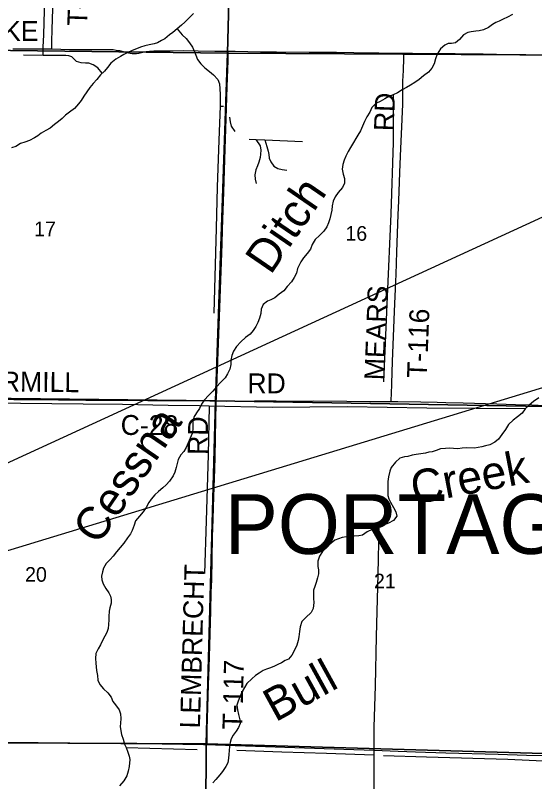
# Model space of a CAD drawing. Extents: x 0 to 39.4, y 0 to 22.
# Drawn here: x 6.833 to 8.317, y 17.227 to 19.416 of the extents above; entities that cross this region are included whole.
import ezdxf

# ---------------------------------------------------------------- set-up
doc = ezdxf.new("R2010")
doc.units = 0
for name, color, linetype in [('GM_X_County_Road', 7, 'Continuous'), ('GM_X_County_Road_Text', 7, 'Continuous'), ('GM_X_Major_River', 7, 'Continuous'), ('GM_X_Minor_River', 7, 'Continuous'), ('GM_X_Minor_River_Text', 7, 'Continuous'), ('GM_X_Section', 7, 'Continuous'), ('GM_X_Section_Text', 7, 'Continuous'), ('GM_X_State_Route', 7, 'Continuous'), ('GM_X_Township_Road', 7, 'Continuous'), ('GM_X_Township_Road_Text', 7, 'Continuous'), ('GM_X_Township_Text', 7, 'Continuous'), ('SH_Data', 7, 'Continuous')]:
    doc.layers.add(name, color=color, linetype=linetype)

msp = doc.modelspace()

# ---------------------------------------------------------------- linework, layer by layer
at = {"layer": 'GM_X_County_Road'}
for points in [[(6.5182, 18.3248), (6.5212, 18.3248), (6.5771, 18.3229), (6.6237, 18.3216), (6.6517, 18.3211), (6.6735, 18.3207), (6.7232, 18.3201), (6.776, 18.3197), (6.8289, 18.3189), (6.8693, 18.3188), (6.9563, 18.3179), (7.0061, 18.3174), (7.034, 18.3171), (7.0962, 18.3169), (7.1304, 18.3168), (7.2112, 18.316), (7.2672, 18.3155), (7.3884, 18.3148), (7.407, 18.3146)], [(7.407, 18.3146), (7.435, 18.3143), (7.5159, 18.3146), (7.578, 18.3146), (7.6309, 18.3144), (7.6837, 18.3145), (7.7801, 18.314), (7.8454, 18.3134), (7.8951, 18.3132), (7.9066, 18.3132)], [(7.9066, 18.3132), (7.9262, 18.3132), (7.9915, 18.3125), (8.0381, 18.3111), (8.0629, 18.3103), (8.1127, 18.3094), (8.209, 18.3066), (8.2618, 18.3048), (8.3084, 18.3031), (8.3643, 18.3008), (8.3985, 18.2993), (8.4075, 18.2991)]]:
    msp.add_lwpolyline(points, dxfattribs=at)
at = {"layer": 'GM_X_Major_River'}
msp.add_lwpolyline([(7.3417, 19.4215), (7.3297, 19.4088), (7.3169, 19.3969), (7.3072, 19.3879), (7.2949, 19.3779), (7.2825, 19.3671), (7.2729, 19.3604), (7.2598, 19.3493), (7.2502, 19.3445), (7.2394, 19.3379), (7.2299, 19.3343), (7.2154, 19.3315), (7.2032, 19.3294), (7.1906, 19.3251), (7.1791, 19.3204), (7.1665, 19.316), (7.1538, 19.3102), (7.1431, 19.3043), (7.1331, 19.2984), (7.1204, 19.2906), (7.1061, 19.2799), (7.0964, 19.2675), (7.0871, 19.2571), (7.0759, 19.2459), (7.0658, 19.2331), (7.0553, 19.2216), (7.046, 19.2103), (7.0374, 19.198), (7.0288, 19.1852), (7.0206, 19.1732), (7.0136, 19.1634), (7.0019, 19.1504), (6.9877, 19.1392), (6.9761, 19.1311), (6.9661, 19.121), (6.9557, 19.1132), (6.9449, 19.1047), (6.9325, 19.0939), (6.9198, 19.0873), (6.9068, 19.0791), (6.8968, 19.0717), (6.8871, 19.0658), (6.873, 19.0585), (6.8596, 19.0534), (6.8477, 19.0502), (6.8343, 19.0413), (6.822, 19.0377)], dxfattribs=at)
at = {"layer": 'GM_X_Minor_River'}
for points in [[(6.9125, 19.3014), (6.9126, 19.3254), (6.9144, 19.3606), (6.9178, 19.5003), (6.9234, 19.6787), (6.9272, 19.8187), (6.9336, 19.9971), (6.9375, 20.1455)], [(8.2535, 19.4186), (8.2397, 19.4113), (8.227, 19.4051), (8.2155, 19.3999), (8.2059, 19.3959), (8.1963, 19.3904), (8.1852, 19.3815), (8.1706, 19.3746), (8.1584, 19.3721), (8.1489, 19.3712), (8.1355, 19.3695), (8.1256, 19.367), (8.1133, 19.3604), (8.1021, 19.347), (8.0909, 19.3377), (8.0791, 19.3356), (8.0696, 19.3354), (8.06, 19.331), (8.048, 19.3202), (8.0382, 19.3052), (8.0334, 19.2916), (8.0297, 19.2773), (8.0234, 19.2656), (8.0133, 19.2536), (7.9994, 19.2429), (7.9871, 19.2332), (7.974, 19.2244), (7.9621, 19.217), (7.9502, 19.21), (7.9379, 19.2034), (7.9248, 19.1949), (7.9129, 19.189), (7.9003, 19.1839), (7.8888, 19.1773), (7.8757, 19.17), (7.8631, 19.1645), (7.8515, 19.1529), (7.8455, 19.1397), (7.8377, 19.1262), (7.8302, 19.1127), (7.825, 19.0999), (7.8187, 19.0863), (7.812, 19.0743), (7.8054, 19.0641), (7.7991, 19.0525), (7.7908, 19.039), (7.7838, 19.0269), (7.7771, 19.0142), (7.7723, 19.0025), (7.769, 18.99), (7.7665, 18.9764), (7.7693, 18.9627), (7.7736, 18.95), (7.7737, 18.9364), (7.7678, 18.9239), (7.7558, 18.9105), (7.7472, 18.8977), (7.7408, 18.8853), (7.7383, 18.8717), (7.7369, 18.8596), (7.7344, 18.8471), (7.7312, 18.835), (7.7275, 18.8237), (7.7227, 18.8116), (7.7145, 18.7996), (7.7018, 18.7869), (7.6898, 18.7761), (7.6808, 18.7619), (7.6767, 18.7479), (7.6666, 18.7355), (7.6561, 18.7236), (7.6491, 18.7119), (7.6388, 18.6931), (7.6359, 18.6799), (7.63, 18.6675), (7.6218, 18.6551)], [(7.2949, 19.3779), (7.3095, 19.3603), (7.3207, 19.3498), (7.3303, 19.3375), (7.3388, 19.3248), (7.345, 19.3118), (7.3483, 19.3022), (7.3537, 19.2904), (7.363, 19.2777), (7.3742, 19.2664), (7.3873, 19.2556), (7.3993, 19.2462), (7.4112, 19.2331), (7.4166, 19.2201), (7.417, 19.206), (7.418, 19.1901)], [(6.9775, 19.3014), (6.9125, 19.3014), (6.8563, 19.3025)], [(7.0805, 19.2505), (7.0684, 19.2663), (7.0548, 19.2749), (7.0432, 19.2797), (7.0333, 19.2799), (7.0211, 19.2808), (7.0072, 19.2841), (6.9945, 19.2977), (6.9852, 19.3007), (6.9775, 19.3014)], [(7.418, 19.1901), (7.4185, 19.1566), (7.4147, 19.0591), (7.4099, 18.9252), (7.4066, 18.8086), (7.4002, 18.5653)], [(7.9129, 19.189), (7.9127, 19.0531), (7.9054, 18.8489), (7.8957, 18.6132), (7.885, 18.3692)], [(7.4185, 19.1566), (7.428, 19.1565)], [(7.4449, 19.1254), (7.4465, 19.1117), (7.4497, 19.0995), (7.46, 19.0845)], [(7.501, 19.0625), (7.5204, 19.0618), (7.5458, 19.0601), (7.6532, 19.0555)], [(7.5204, 19.0618), (7.5322, 19.0437), (7.5339, 19.0307), (7.5333, 19.0197), (7.5327, 19.0103), (7.5283, 18.9963), (7.5251, 18.9865), (7.5203, 18.9744), (7.5174, 18.9608), (7.5183, 18.9486), (7.5207, 18.936)], [(7.5458, 19.0601), (7.5519, 19.0414), (7.5551, 19.0281), (7.5568, 19.0182), (7.5585, 19.0079), (7.5625, 18.9979), (7.571, 18.9849), (7.5827, 18.9786), (7.5955, 18.9761), (7.6084, 18.9743)], [(7.6218, 18.6551), (7.6094, 18.6416), (7.6, 18.6293), (7.5869, 18.6196), (7.5742, 18.6096), (7.5627, 18.6037), (7.5531, 18.5997), (7.5412, 18.5905), (7.5356, 18.5769), (7.5339, 18.5648), (7.5302, 18.5515), (7.5258, 18.5387), (7.5202, 18.527), (7.5128, 18.5154), (7.5035, 18.5057), (7.4904, 18.4957), (7.4776, 18.4834), (7.4652, 18.4699), (7.4562, 18.4568), (7.4511, 18.4444), (7.4489, 18.4307), (7.4483, 18.419), (7.4462, 18.4057), (7.4395, 18.3925), (7.432, 18.3805), (7.4193, 18.3678), (7.408, 18.3548), (7.3971, 18.3428), (7.3847, 18.3305), (7.3731, 18.3178), (7.3645, 18.3058), (7.359, 18.293), (7.35, 18.281), (7.3426, 18.2686), (7.3397, 18.2569), (7.3403, 18.2474), (7.34, 18.2329), (7.3379, 18.2216), (7.3319, 18.208), (7.3271, 18.1952), (7.3208, 18.1813), (7.3138, 18.17), (7.3056, 18.1603), (7.2981, 18.1471), (7.2956, 18.1358), (7.2928, 18.1248), (7.2887, 18.1108), (7.284, 18.1006), (7.2731, 18.0857), (7.2637, 18.0752), (7.2541, 18.0662), (7.2417, 18.0562), (7.2317, 18.0469), (7.2208, 18.0338), (7.2138, 18.0241), (7.2063, 18.0098), (7.1985, 17.9977), (7.188, 17.9858), (7.1763, 17.9723), (7.1727, 17.9595), (7.1663, 17.9444), (7.1616, 17.9346), (7.1534, 17.9234), (7.1429, 17.9084), (7.1327, 17.8956), (7.1223, 17.8837), (7.1122, 17.8717), (7.104, 17.862), (7.0924, 17.8504), (7.0849, 17.8369), (7.0817, 17.8267), (7.0792, 17.8138), (7.0801, 17.8035), (7.0841, 17.7921), (7.0918, 17.779), (7.1, 17.7667), (7.1047, 17.7567), (7.1068, 17.7472), (7.107, 17.7373), (7.103, 17.7241), (7.1013, 17.7139), (7.1002, 17.6987), (7.0997, 17.6892), (7.0994, 17.6763), (7.0981, 17.6646), (7.0944, 17.6528), (7.0889, 17.6427), (7.083, 17.6322), (7.0759, 17.6182), (7.0696, 17.6062), (7.0625, 17.593), (7.0615, 17.5786), (7.0628, 17.5657), (7.0637, 17.555), (7.0651, 17.5451), (7.0671, 17.5303), (7.0687, 17.5173), (7.0742, 17.5051), (7.0846, 17.4927), (7.0969, 17.4811), (7.107, 17.4684)], [(8.3292, 18.3237), (8.3138, 18.3129), (8.301, 18.3029), (8.2895, 18.2925), (8.2813, 18.2801), (8.2678, 18.2693), (8.2554, 18.2597), (8.2423, 18.2477), (8.2333, 18.2327), (8.2231, 18.2185), (8.2134, 18.205), (8.203, 18.1972), (8.1892, 18.1894), (8.1766, 18.1866), (8.1659, 18.1834), (8.1556, 18.1817), (8.1445, 18.18), (8.1214, 18.1804), (8.1099, 18.1795), (8.097, 18.1782), (8.0849, 18.1788), (8.0739, 18.1801), (8.0617, 18.1788), (8.048, 18.1783), (8.0353, 18.1732), (8.0243, 18.1692), (8.0147, 18.1686), (8.0052, 18.1658), (7.9915, 18.1637), (7.9785, 18.1613), (7.9667, 18.1593), (7.9549, 18.1564), (7.9449, 18.1547), (7.932, 18.1515), (7.9188, 18.14), (7.9068, 18.125), (7.9028, 18.1137), (7.8991, 18.0978), (7.8977, 18.0849), (7.8971, 18.0716), (7.8969, 18.0598), (7.8977, 18.0446), (7.9002, 18.0347), (7.9046, 18.0251), (7.9131, 18.0102), (7.9197, 17.9975), (7.9229, 17.9857), (7.9139, 17.9729), (7.8994, 17.9656), (7.8898, 17.962), (7.8768, 17.9573), (7.8653, 17.9529), (7.8523, 17.9478), (7.8381, 17.9405)], [(8.2895, 18.2925), (8.009, 18.2944), (7.7819, 18.2978), (7.5668, 18.296), (7.3865, 18.2997), (7.3591, 18.3006), (7.2691, 18.3018), (7.1389, 18.3046), (7.0268, 18.3051), (6.8479, 18.3072), (6.7195, 18.3096)], [(7.3865, 18.2997), (7.3839, 18.1604), (7.3784, 17.9721), (7.373, 17.8217)], [(7.872, 17.9555), (7.8691, 17.8199), (7.8643, 17.6422), (7.8609, 17.5006), (7.8572, 17.3826), (7.8568, 17.3024), (7.8562, 17.1041), (7.8559, 16.8838), (7.8556, 16.7266), (7.8557, 16.5477), (7.8535, 16.4075), (7.8507, 16.3214), (7.7334, 16.322), (7.6118, 16.3215)], [(7.8381, 17.9405), (7.8246, 17.9316), (7.814, 17.9291), (7.8006, 17.9286), (7.7896, 17.9277), (7.7789, 17.9264), (7.7671, 17.9243), (7.756, 17.9211), (7.7461, 17.9167), (7.7353, 17.9081), (7.7218, 17.8966), (7.7102, 17.8843), (7.7016, 17.8711), (7.6975, 17.8568), (7.6968, 17.8416), (7.699, 17.8321), (7.6987, 17.8207), (7.6967, 17.8097), (7.6926, 17.7961), (7.6886, 17.7848), (7.685, 17.7738), (7.6848, 17.7609), (7.6849, 17.7503), (7.6859, 17.7392), (7.684, 17.7218), (7.6785, 17.7105), (7.6631, 17.6963), (7.6511, 17.6844), (7.647, 17.6693), (7.6452, 17.6564), (7.6427, 17.6412), (7.641, 17.6306), (7.6369, 17.617), (7.6306, 17.6023), (7.6231, 17.5888), (7.6134, 17.5772), (7.6038, 17.5728), (7.5938, 17.5661), (7.5827, 17.5618), (7.5731, 17.5566), (7.5621, 17.5523), (7.5506, 17.5483), (7.541, 17.5443), (7.5291, 17.5369), (7.5187, 17.5299), (7.5083, 17.5206), (7.4947, 17.5075), (7.4881, 17.4959), (7.481, 17.4842), (7.4751, 17.4714), (7.4695, 17.4574), (7.4659, 17.4457), (7.4679, 17.4324), (7.4704, 17.4194), (7.4743, 17.4042), (7.4748, 17.3935), (7.4704, 17.3822), (7.4638, 17.3717), (7.4548, 17.3601), (7.4497, 17.3495), (7.4469, 17.3386), (7.4448, 17.328), (7.4438, 17.3166), (7.4428, 17.3045), (7.4423, 17.2946), (7.4397, 17.2813), (7.4342, 17.27), (7.4252, 17.2565), (7.4175, 17.2468), (7.4055, 17.2337), (7.3969, 17.224)], [(7.107, 17.4684), (7.1117, 17.4558), (7.1191, 17.4461), (7.1295, 17.4323), (7.1334, 17.4204), (7.1343, 17.4071), (7.1329, 17.3942), (7.1324, 17.3847), (7.134, 17.3722), (7.1365, 17.3619), (7.1408, 17.3481), (7.1451, 17.334), (7.1491, 17.3244), (7.1542, 17.3118), (7.1581, 17.3), (7.1595, 17.29), (7.1576, 17.2703), (7.1551, 17.2571), (7.1514, 17.2439), (7.1424, 17.2292), (7.1304, 17.215)], [(7.1491, 17.3244), (7.3526, 17.3188)], [(7.8568, 17.3024), (7.722, 17.3072), (7.5941, 17.3114), (7.4662, 17.316)], [(8.6181, 17.2813), (8.4837, 17.2849), (8.3618, 17.2848), (8.2399, 17.2905), (8.0075, 17.297), (7.8849, 17.3008)]]:
    msp.add_lwpolyline(points, dxfattribs=at)
at = {"layer": 'GM_X_Section'}
for points in [[(6.4661, 20.3227), (7.4647, 20.3092), (7.439, 19.3083), (6.4302, 19.3208)], [(8.4681, 20.3039), (8.4416, 19.3027), (7.439, 19.3083), (7.4647, 20.3092)], [(6.4302, 19.3208), (7.439, 19.3083), (7.4046, 18.3152), (6.4032, 18.3261)], [(8.4416, 19.3027), (8.401, 18.2978), (7.4046, 18.3152), (7.439, 19.3083)], [(7.4046, 18.3152), (7.3784, 17.3348), (6.3887, 17.3403), (6.4032, 18.3261)], [(8.401, 18.2978), (8.3769, 17.3064), (7.3784, 17.3348), (7.4046, 18.3152)], [(7.3784, 17.3348), (7.3732, 16.344), (6.3716, 16.3557), (6.3887, 17.3403)], [(8.3769, 17.3064), (8.3707, 16.3273), (7.3732, 16.344), (7.3784, 17.3348)]]:
    msp.add_lwpolyline(points, close=True, dxfattribs=at)
at = {"layer": 'GM_X_State_Route'}
msp.add_lwpolyline([(6.8016, 17.3392), (6.898, 17.3386), (6.9881, 17.3378), (7.0534, 17.3371), (7.1342, 17.3365), (7.1933, 17.3358), (7.3704, 17.3333), (7.3804, 17.3331), (7.4046, 17.3325), (7.4605, 17.3304), (7.5195, 17.3285), (7.5755, 17.3267), (7.7712, 17.3196), (7.8582, 17.3167), (7.9265, 17.3146), (7.9762, 17.3125), (8.0632, 17.3097), (8.2123, 17.3053), (8.2931, 17.3024), (8.3824, 17.3006)], dxfattribs=at)
at = {"layer": 'GM_X_Township_Road'}
for points in [[(6.9367, 19.3202), (6.9367, 19.3221), (6.9367, 19.3293), (6.9367, 19.3413), (6.9378, 19.3761), (6.9401, 19.4351), (6.9432, 19.5251), (6.9465, 19.6058), (6.9483, 19.6648), (6.9499, 19.7083), (6.9509, 19.7393), (6.9537, 19.8169), (6.9571, 19.9256), (6.9614, 20.0746), (6.9635, 20.1429), (6.9647, 20.1957), (6.9662, 20.2641), (6.9673, 20.2982), (6.9682, 20.3136)], [(6.8256, 19.3203), (6.8417, 19.3206), (6.8604, 19.3207), (6.8852, 19.3205), (6.907, 19.3203), (6.9367, 19.3202)], [(6.9367, 19.3202), (6.938, 19.3202), (6.9628, 19.3194), (6.9876, 19.319), (7.0218, 19.3188), (7.0498, 19.3187), (7.0746, 19.3184), (7.0871, 19.3187), (7.1026, 19.3188), (7.1119, 19.3183), (7.1211, 19.317), (7.1303, 19.3153), (7.1515, 19.3103), (7.1606, 19.3084), (7.1668, 19.3076), (7.173, 19.3073), (7.1792, 19.3074), (7.1853, 19.3082), (7.1975, 19.311), (7.2067, 19.3126), (7.2159, 19.3136), (7.2283, 19.3143), (7.2749, 19.315), (7.3122, 19.3154), (7.3557, 19.3144), (7.4024, 19.3142), (7.4416, 19.3138)], [(7.407, 18.3146), (7.4072, 18.3209), (7.4092, 18.3799), (7.412, 18.4544), (7.4167, 18.5817), (7.4196, 18.6593), (7.4225, 18.7369), (7.4237, 18.7648), (7.425, 18.8021), (7.4261, 18.8331), (7.427, 18.8579), (7.4287, 18.9107), (7.4319, 19.0039), (7.4355, 19.1219), (7.4383, 19.2119), (7.4407, 19.2864), (7.4414, 19.3082), (7.4416, 19.3138)], [(7.4416, 19.3138), (7.4614, 19.3137), (7.5329, 19.3122), (7.5795, 19.3119), (7.6728, 19.311), (7.7505, 19.3106), (7.8002, 19.3097), (7.8717, 19.309), (7.9433, 19.3081)], [(7.921, 18.6756), (7.9233, 18.7405), (7.9271, 18.846), (7.9287, 18.8864), (7.932, 18.9671), (7.9337, 19.0136), (7.938, 19.1192), (7.94, 19.1626), (7.9404, 19.1813), (7.94, 19.2061), (7.9403, 19.2278), (7.9418, 19.2589), (7.9431, 19.2939), (7.9431, 19.2975), (7.9432, 19.3024), (7.9433, 19.3081)], [(7.9433, 19.3081), (7.9681, 19.3078), (8.0147, 19.3076), (8.0396, 19.3072), (8.0893, 19.3067), (8.1328, 19.306), (8.1701, 19.3058), (8.2074, 19.3052), (8.2913, 19.304), (8.397, 19.3031), (8.4405, 19.3033), (8.4422, 19.3032)], [(7.9066, 18.3132), (7.9068, 18.3183), (7.9073, 18.3338), (7.9084, 18.3649), (7.911, 18.427), (7.9167, 18.5697), (7.9203, 18.6566), (7.921, 18.6756)], [(7.3804, 17.3331), (7.3806, 17.3376), (7.3808, 17.3467), (7.3814, 17.3761), (7.3849, 17.5037), (7.3864, 17.5534), (7.3882, 17.6156), (7.391, 17.7152), (7.3926, 17.7681), (7.3939, 17.8023), (7.3954, 17.8645), (7.3965, 17.9267), (7.3981, 17.9765), (7.4003, 18.0418), (7.4026, 18.1195), (7.4035, 18.1538), (7.4058, 18.2627), (7.4069, 18.3062), (7.407, 18.3146)]]:
    msp.add_lwpolyline(points, dxfattribs=at)
at = {"layer": 'SH_Data'}
msp.add_lwpolyline([(9.4615, 18.6937), (5.1869, 17.3921), (9.4615, 19.3557)], close=True, dxfattribs=at)

# ---------------------------------------------------------------- texts
at = {"layer": 'GM_X_County_Road_Text'}
for s, rotation, p in [('MERMILL', 359.4049, (6.6771, 18.343)), ('RD', 0, (7.4959, 18.3364)), ('C-28', 359.6571, (7.1336, 18.2177))]:
    msp.add_text(s, height=0.05682, rotation=rotation, dxfattribs=at).set_placement(p)
at = {"layer": 'GM_X_Minor_River_Text'}
for s, rotation, p in [('Ditch', 55.5712, (7.5623, 18.6723)), ('Cessna', 55.581, (7.0694, 17.8999)), ('Creek', 10.8327, (7.9728, 18.0186)), ('Bull', 28.8366, (7.576, 17.396))]:
    msp.add_text(s, height=0.09475, rotation=rotation, dxfattribs=at).set_placement(p)
at = {"layer": 'GM_X_Section_Text'}
for s, p in [('17', (6.8863, 18.7853)), ('16', (7.7759, 18.7723)), ('20', (6.8605, 17.7982)), ('21', (7.8576, 17.7793))]:
    msp.add_text(s, height=0.04186, rotation=0, dxfattribs=at).set_placement(p)
at = {"layer": 'GM_X_Township_Road_Text'}
for s, rotation, p in [('T-173', 88.0503, (7.0378, 19.3853)), ('PIKE', 0, (6.7259, 19.343)), ('RD', 88.1276, (7.9144, 19.0847)), ('MEARS', 87.812, (7.8869, 18.3731)), ('T-116', 87.7544, (8.0086, 18.3792)), ('RD', 89.0127, (7.3819, 18.1601)), ('LEMBRECHT', 88.4146, (7.3602, 17.3786)), ('T-117', 88.5957, (7.4812, 17.3757))]:
    msp.add_text(s, height=0.05682, rotation=rotation, dxfattribs=at).set_placement(p)
at = {"layer": 'GM_X_Township_Text'}
msp.add_text('PORTAGE', height=0.17045, rotation=0, dxfattribs=at).set_placement((7.4309, 17.8777))

doc.saveas('drawing.dxf')
